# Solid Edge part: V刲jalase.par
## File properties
Author: Türk
Template: iso part.par
Last saved by: Türk
Revision: 33
Application: Solid Edge
Accuracy: 0,990
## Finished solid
Body 1: sheet body, 1 face, 4 edges, 4 vertices.
  Faces by surface: plane 1
  Edges by curve: ellipse 2, intersection 2
Body 2: sheet body, 1 face, 2 edges, 0 vertices.
  Faces by surface: plane 1
  Edges by curve: circle 2
Body 3: sheet body, 1 face, 2 edges, 0 vertices.
  Faces by surface: plane 1
  Edges by curve: circle 2
Body 4: sheet body, 5 faces, 10 edges, 0 vertices.
  Faces by surface: plane 5
  Edges by curve: circle 10
Body 5: sheet body, 5 faces, 10 edges, 0 vertices.
  Faces by surface: plane 5
  Edges by curve: intersection 10
Body 6: sheet body, 5 faces, 80 edges, 80 vertices.
  Faces by surface: plane 5
  Edges by curve: curve on surface 80
Body 7: sheet body, 4 faces, 20 edges, 16 vertices.
  Faces by surface: plane 4
  Edges by curve: line 7, intersection 6, circle 4, ellipse 3
Body 8: solid body, 279 faces, 826 edges, 573 vertices.
  Faces by surface: plane 112, cylinder 105, torus 28, spline 20, blend 14
  Edges by curve: line 358, circle 285, curve on surface 101, intersection 54, ellipse 28
Bounding box of the edges (mm; curved faces can reach further): 999.322 x 797.645 x 306.222, from (-691.3225, -792.6449, -18.043) to (308, 5, 288.1793).
Cylindrical faces by radius (mm): R3.5 x20, R5 x20, R8.5 x32, R10 x10, R15 x2, R19.9997 x1, R20 x5, R20.0006 x4, R22 x9, R25 x1, R30 x1
Toroidal faces (ring radius, tube radius in mm): R22 r20.0006 x1, R22 r22 x1, R42.8392 r20.0006 x1, R42.8392 r22 x1, R59.886 r20.0006 x1, R59.886 r22 x1, R119.9881 r20 x1, R119.9881 r22 x1, R119.99 r20 x1, R119.99 r22 x1, R119.9907 r19.9997 x1, R119.9907 r22 x1, R120.0095 r20.0006 x1, R120.0095 r22 x1, R120.0119 r20 x1, R120.0119 r22 x1, R149.9997 r19.9997 x1, R149.9997 r22 x1, R150 r20 x3, R150 r22 x3, R150.0006 r20.0006 x1, R150.0006 r22 x1, R197.138 r20.0006 x1, R197.138 r22 x1
Planar faces by outward normal: +x 15, +y 1, +z 29, -x 16, -y 1, -z 27, oblique 23
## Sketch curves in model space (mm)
circle centre (45.8597, -133.541, 145.9577) radius 20
circle centre (32.3889, -175, 145.9577) radius 20
circle centre (-11.2037, -175, 145.9577) radius 20
circle centre (-24.6745, -133.541, 145.9577) radius 20
circle centre (10.5926, -107.918, 145.9577) radius 20
line (8.7963, -175, 145.9577) -> (12.3889, -175, 145.9577)
line (29.6794, -121.7853, 145.9577) -> (26.7729, -119.6737, 145.9577)
line (38.5692, -155.9789, 145.9577) -> (39.6794, -152.5621, 145.9577)
line (-5.5877, -119.6737, 145.9577) -> (-8.4942, -121.7853, 145.9577)
line (-8.4942, -121.7853, 145.9577) -> (-5.5877, -119.6737, 145.9577)
line (-18.4942, -152.5621, 145.9577) -> (-17.384, -155.9789, 145.9577)
line (-17.384, -155.9789, 145.9577) -> (-18.4942, -152.5621, 145.9577)
line (32.3889, -175, 145.9577) -> (88.5081, -175, 145.9577)
arc centre (88.5081, -75, 145.9577) radius 100 from (88.5081, -175, 145.9577) through (111.7357, -172.265, 145.9577) to (133.6928, -164.2095, 145.9577)
line (133.6928, -164.2095, 145.9577) -> (195.7766, -132.764, 145.9577)
arc centre (150.5918, -43.5545, 145.9577) radius 100 from (250.5918, -43.5545, 145.9577) through (235.793, -95.9068, 145.9577) to (195.7766, -132.764, 145.9577)
line (250.5918, -25, 145.9577) -> (250.5918, -43.5545, 145.9577)
line (45.8597, -133.541, 145.9577) -> (90.536, -133.541, 145.9577)
arc centre (90.536, -108.541, 145.9577) radius 25 from (90.536, -133.541, 145.9577) through (103.6008, -129.8556, 145.9577) to (112.8136, -119.886, 145.9577)
line (112.8136, -119.886, 145.9577) -> (127.8571, -90.3459, 145.9577)
arc centre (105.5796, -79.0009, 145.9577) radius 25 from (130.5796, -79.0009, 145.9577) through (129.8894, -84.8344, 145.9577) to (127.8571, -90.3459, 145.9577)
line (130.5796, -25, 145.9577) -> (130.5796, -79.0009, 145.9577)
line (-229.4066, -43.5545, 145.9577) -> (-228.5045, -25, 145.9577)
arc centre (-129.4066, -43.5545, 145.9577) radius 100 from (-229.4066, -43.5545, 145.9577) through (-214.6078, -95.9068, 145.9577) to (-174.5914, -132.764, 145.9577)
line (-112.5076, -164.2095, 145.9577) -> (-174.5914, -132.764, 145.9577)
arc centre (-67.3229, -75, 145.9577) radius 100 from (-67.3229, -175, 145.9577) through (-90.5505, -172.265, 145.9577) to (-112.5076, -164.2095, 145.9577)
line (-11.2037, -175, 145.9577) -> (-67.3229, -175, 145.9577)
line (-109.3944, -79.0009, 145.9577) -> (-109.3966, -25, 145.9577)
arc centre (-84.3944, -79.0009, 145.9577) radius 25 from (-109.3944, -79.0009, 145.9577) through (-108.7042, -84.8344, 145.9577) to (-106.6719, -90.3459, 145.9577)
line (-91.6284, -119.886, 145.9577) -> (-106.6719, -90.3459, 145.9577)
arc centre (-69.3508, -108.541, 145.9577) radius 25 from (-69.3508, -133.541, 145.9577) through (-82.4156, -129.8556, 145.9577) to (-91.6284, -119.886, 145.9577)
line (-24.6745, -133.541, 145.9577) -> (-69.3508, -133.541, 145.9577)
line (-516.6626, -312.1214, 161.029) -> (-474.2784, -312.1784, 203.4975)
line (-515.4024, -272.1594, 159.8248) -> (-516.6626, -312.1214, 161.029)
line (-467.9433, -269.2353, 207.1937) -> (-515.4024, -272.1594, 159.8248)
line (-228, -145.2082, 33.7496) -> (-228, -116.9239, 62.0338)
line (-347.99, -131.066, 47.8917) -> (-347.99, -158.8246, 20.1331)
line (-107.9881, -145.2082, 33.7496) -> (-107.9881, -116.9239, 62.0338)
line (12, -145.2082, 33.7496) -> (12, -112.5625, 66.3953)
line (131.9907, -146.6222, 32.3356) -> (131.9907, -116.9239, 62.0338)
line (32.3889, -175, 145.9577) -> (32.3889, -175, 130.5516)
arc centre (72.3889, -175, 130.5516) radius 40 from (66.6213, -175, 90.9696) through (42.1341, -175, 104.3859) to (32.3889, -175, 130.5516)
line (66.6213, -175, 90.9696) -> (217.7676, -175, 68.9458)
arc centre (212, -175, 29.3638) radius 40 from (252, -175, 29.3638) through (242.2548, -175, 55.5296) to (217.7676, -175, 68.9458)
line (252, -175, 3.9577) -> (252, -175, 29.3638)
line (-541.5458, -560.1002, 253.4667) -> (-626.6813, -546.8463, 252.446)
line (12, -25, 153.9577) -> (-83.1514, -25, 153.9577)
line (-428, -270.4641, 247.2889) -> (-428, -179.7146, 241.687)
line (-428, -270.4641, 187.2889) -> (-428, -270.4641, 247.2889)
line (-428, -270.4641, 187.2889) -> (-428, -192.1667, 187.2889)
line (-228.5045, 0, 145.9577) -> (250.5918, 0, 145.9577)
arc centre (229.5, 0, 15.4577) radius 8.5 from (221, 0, 15.4577) through (223.6669, 0, 21.6404) to (229.5, 0, 23.9577)
line (221, 0, 13.9577) -> (221, 0, 15.4577)
arc centre (216, 0, 13.9577) radius 5 from (216, 0, 8.9577) through (219.6369, 0, 10.5265) to (221, 0, 13.9577)
line (200.6603, 0, 8.9577) -> (216, 0, 8.9577)
arc centre (192, 0, 3.9577) radius 10 from (183.3397, 0, 8.9577) through (192.2992, 0, 13.9532) to (200.6603, 0, 8.9577)
line (168, 0, 8.9577) -> (183.3397, 0, 8.9577)
arc centre (168, 0, 13.9577) radius 5 from (163, 0, 13.9577) through (164.5688, 0, 10.3208) to (168, 0, 8.9577)
line (163, 0, 15.4577) -> (163, 0, 13.9577)
arc centre (154.5, 0, 15.4577) radius 8.5 from (154.5, 0, 23.9577) through (160.6827, 0, 21.2908) to (163, 0, 15.4577)
line (136.5, 0, 23.9577) -> (154.5, 0, 23.9577)
arc centre (136.5, 0, 15.4577) radius 8.5 from (136.2307, 0, 23.9534) through (136.3653, 0, 23.9566) to (136.5, 0, 23.9577)
line (131.9881, 0, 23.9538) -> (136.2307, 0, 23.9534)
line (127.7455, 0, 23.9534) -> (131.9881, 0, 23.9538)
arc centre (127.4762, 0, 15.4577) radius 8.5 from (127.4762, 0, 23.9577) through (127.6109, 0, 23.9566) to (127.7455, 0, 23.9534)
line (109.4762, 0, 23.9577) -> (127.4762, 0, 23.9577)
arc centre (109.4762, 0, 15.4577) radius 8.5 from (100.9762, 0, 15.4577) through (103.6432, 0, 21.6404) to (109.4762, 0, 23.9577)
line (100.9762, 0, 13.9577) -> (100.9762, 0, 15.4577)
arc centre (95.9762, 0, 13.9577) radius 5 from (95.9762, 0, 8.9577) through (99.6131, 0, 10.5265) to (100.9762, 0, 13.9577)
line (80.6365, 0, 8.9577) -> (95.9762, 0, 8.9577)
arc centre (71.9762, 0, 3.9577) radius 10 from (63.316, 0, 8.9577) through (72.2754, 0, 13.9532) to (80.6365, 0, 8.9577)
line (47.9762, 0, 8.9577) -> (63.316, 0, 8.9577)
arc centre (47.9762, 0, 13.9577) radius 5 from (42.9762, 0, 13.9577) through (44.545, 0, 10.3208) to (47.9762, 0, 8.9577)
line (42.9762, 0, 15.4577) -> (42.9762, 0, 13.9577)
arc centre (34.4762, 0, 15.4577) radius 8.5 from (34.4762, 0, 23.9577) through (40.6589, 0, 21.2908) to (42.9762, 0, 15.4577)
line (16.4762, 0, 23.9577) -> (34.4762, 0, 23.9577)
arc centre (16.4762, 0, 15.4577) radius 8.5 from (16.2069, 0, 23.9534) through (16.3415, 0, 23.9566) to (16.4762, 0, 23.9577)
line (12.0357, 0, 23.9538) -> (16.2069, 0, 23.9534)
line (7.7931, 0, 23.9534) -> (12.0357, 0, 23.9538)
arc centre (7.5238, 0, 15.4577) radius 8.5 from (7.5238, 0, 23.9577) through (7.6585, 0, 23.9566) to (7.7931, 0, 23.9534)
line (-10.4762, 0, 23.9577) -> (7.5238, 0, 23.9577)
arc centre (-10.4762, 0, 15.4577) radius 8.5 from (-18.9762, 0, 15.4577) through (-16.3093, 0, 21.6404) to (-10.4762, 0, 23.9577)
line (-18.9762, 0, 13.9577) -> (-18.9762, 0, 15.4577)
arc centre (-23.9762, 0, 13.9577) radius 5 from (-23.9762, 0, 8.9577) through (-20.3393, 0, 10.5265) to (-18.9762, 0, 13.9577)
line (-39.316, 0, 8.9577) -> (-23.9762, 0, 8.9577)
arc centre (-47.9762, 0, 3.9577) radius 10 from (-56.6365, 0, 8.9577) through (-47.6771, 0, 13.9532) to (-39.316, 0, 8.9577)
line (298, 0, -6.0423) -> (298, 0, -11.0419)
arc centre (293, 0, -11.0419) radius 5 from (298, 0, -11.0419) through (296.431, 0, -14.6789) to (292.9996, 0, -16.0419)
line (292.9996, 0, -16.0419) -> (247.7693, 0, -16.038)
arc centre (247.5, 0, -7.5423) radius 8.5 from (247.7693, 0, -16.038) through (247.6347, 0, -16.0412) to (247.5, 0, -16.0423)
line (247.5, 0, -16.0423) -> (229.5, 0, -16.0423)
arc centre (229.5, 0, -7.5423) radius 8.5 from (229.5, 0, -16.0423) through (223.3173, 0, -13.3753) to (221, 0, -7.5423)
line (221, 0, -7.5423) -> (221, 0, -6.0423)
arc centre (216, 0, -6.0423) radius 5 from (221, 0, -6.0423) through (219.4312, 0, -2.4054) to (216, 0, -1.0423)
line (216, 0, -1.0423) -> (200.6603, 0, -1.0423)
arc centre (192, 0, 3.9577) radius 10 from (200.6603, 0, -1.0423) through (191.7008, 0, -6.0378) to (183.3397, 0, -1.0423)
line (183.3397, 0, -1.0423) -> (168, 0, -1.0423)
arc centre (168, 0, -6.0423) radius 5 from (168, 0, -1.0423) through (164.3631, 0, -2.6111) to (163, 0, -6.0423)
line (163, 0, -6.0423) -> (163, 0, -7.5423)
arc centre (154.5, 0, -7.5423) radius 8.5 from (163, 0, -7.5423) through (160.3331, 0, -13.725) to (154.5, 0, -16.0423)
line (154.5, 0, -16.0423) -> (136.5, 0, -16.0423)
arc centre (136.5, 0, -7.5423) radius 8.5 from (136.5, 0, -16.0423) through (136.3653, 0, -16.0412) to (136.2307, 0, -16.038)
line (136.2307, 0, -16.038) -> (131.9881, 0, -16.0384)
line (131.9881, 0, -16.0384) -> (127.7455, 0, -16.038)
arc centre (127.4762, 0, -7.5423) radius 8.5 from (127.7455, 0, -16.038) through (127.6109, 0, -16.0412) to (127.4762, 0, -16.0423)
line (127.4762, 0, -16.0423) -> (109.4762, 0, -16.0423)
arc centre (109.4762, 0, -7.5423) radius 8.5 from (109.4762, 0, -16.0423) through (103.2935, 0, -13.3753) to (100.9762, 0, -7.5423)
line (100.9762, 0, -7.5423) -> (100.9762, 0, -6.0423)
arc centre (95.9762, 0, -6.0423) radius 5 from (100.9762, 0, -6.0423) through (99.4074, 0, -2.4054) to (95.9762, 0, -1.0423)
line (95.9762, 0, -1.0423) -> (80.6365, 0, -1.0423)
arc centre (71.9762, 0, 3.9577) radius 10 from (80.6365, 0, -1.0423) through (71.6771, 0, -6.0378) to (63.316, 0, -1.0423)
line (63.316, 0, -1.0423) -> (47.9762, 0, -1.0423)
arc centre (47.9762, 0, -6.0423) radius 5 from (47.9762, 0, -1.0423) through (44.3393, 0, -2.6111) to (42.9762, 0, -6.0423)
line (42.9762, 0, -6.0423) -> (42.9762, 0, -7.5423)
arc centre (34.4762, 0, -7.5423) radius 8.5 from (42.9762, 0, -7.5423) through (40.3093, 0, -13.725) to (34.4762, 0, -16.0423)
line (34.4762, 0, -16.0423) -> (16.4762, 0, -16.0423)
arc centre (12.1382, 0, -8.7326) radius 8.5 from (16.4762, 0, -16.0423) through (12.1341, 0, -17.2326) to (7.7931, 0, -16.038)
arc centre (7.5238, 0, -7.5423) radius 8.5 from (7.7931, 0, -16.038) through (7.6585, 0, -16.0412) to (7.5238, 0, -16.0423)
line (7.5238, 0, -16.0423) -> (-10.4762, 0, -16.0423)
arc centre (-10.4762, 0, -7.5423) radius 8.5 from (-10.4762, 0, -16.0423) through (-16.6589, 0, -13.3753) to (-18.9762, 0, -7.5423)
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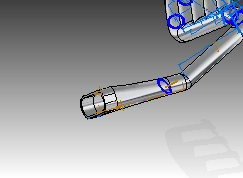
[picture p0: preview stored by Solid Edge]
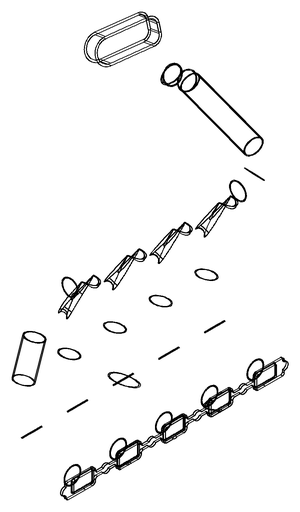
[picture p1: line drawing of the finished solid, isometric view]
